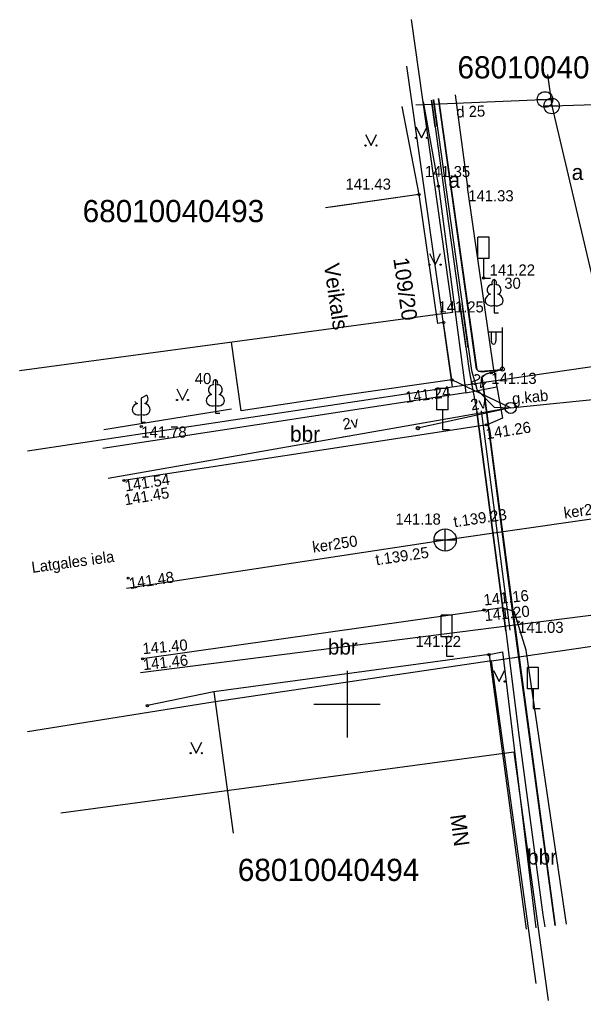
# Model space of a CAD drawing. Extents: x 728785 to 728985, y 273137 to 273208.
# Drawn here: x 728785.24 to 728810.66, y 273136.65 to 273180.84 of the extents above; entities that cross this region are included whole.
import ezdxf

# ---------------------------------------------------------------- set-up
doc = ezdxf.new("R2010")
doc.units = 0
for name, color, linetype in [('APGR_SARK_####_####_#', 7, 'Continuous'), ('APGS_ACRL_####_####_#', 7, 'Continuous'), ('APGS_ELEM_####_####_#', 7, 'Continuous'), ('APGS_VADP_ZSPR_####_I', 7, 'Continuous'), ('BUVE_BDET_####_####_#', 7, 'Continuous'), ('BUVE_EKAS_####_####_#', 7, 'Continuous'), ('BUVE_EKAS_ADRS_TKST_#', 7, 'Continuous'), ('BUVE_EKAS_RAKS_TKST_#', 7, 'Continuous'), ('CELI_CAPM_####_####_#', 7, 'Continuous'), ('CELI_CMAL_####_####_#', 7, 'Continuous'), ('CELI_CSEG_####_TKST_#', 7, 'Continuous'), ('CELI_ELEM_####_####_#', 7, 'Continuous'), ('CELI_IELA_####_TKST_#', 7, 'Continuous'), ('ELEK_ACRL_####_####_#', 7, 'Continuous'), ('ELEK_ELEM_####_####_#', 7, 'Continuous'), ('ELEK_SAIT_####_####_#', 7, 'Continuous'), ('ELEK_SAVL_####_####_#', 7, 'Continuous'), ('ELEK_VADP_ZSPR_####_I', 7, 'Continuous'), ('ELEK_VADV_ZSPR_####_#', 7, 'Continuous'), ('ELEK_VADV_ZSPR_TKST_#', 7, 'Continuous'), ('GEOD_ELEM_####_####_#', 7, 'Continuous'), ('NORB_ZOGS_ZSTP_####_#', 7, 'Continuous'), ('RELJ_AATZ_####_TKST_#', 7, 'Continuous'), ('RELJ_ELEM_####_####_#', 7, 'Continuous'), ('ROBZ_KADS_####_TKST_#', 7, 'Continuous'), ('ROBZ_UZMR_####_####_#', 7, 'Continuous'), ('SAKK_KKAN_####_####_#', 7, 'Continuous'), ('SKAN_ELEM_####_####_#', 7, 'Continuous'), ('SKAN_ELEM_PAST_TKST_#', 7, 'Continuous'), ('SKAN_VADP_PAST_####_#', 7, 'Continuous'), ('SKAN_VADP_PAST_TKST_#', 7, 'Continuous'), ('TERT_DIAM_####_TKST_#', 7, 'Continuous'), ('TERT_DZOG_####_####_#', 7, 'Continuous'), ('TERT_ELEM_####_####_#', 7, 'Continuous'), ('UDTK_ELEM_####_####_#', 7, 'Continuous'), ('UDTK_VADP_UDEN_####_#', 7, 'Continuous'), ('UDTK_VADP_UDEN_TKST_#', 7, 'Continuous')]:
    doc.layers.add(name, color=color, linetype=linetype)

msp = doc.modelspace()

# ---------------------------------------------------------------- linework, layer by layer
at = {"layer": 'APGR_SARK_####_####_#'}
for points in [[(728802.885, 273180.839), (728804.76, 273167.644)], [(728804.76, 273167.644), (728785.239, 273165.014)], [(728807.526, 273147.836), (728787.092, 273145.083)], [(728807.526, 273147.836), (728809.06, 273136.65)]]:
    msp.add_lwpolyline(points, dxfattribs=at)
at = {"layer": 'APGS_ACRL_####_####_#'}
for points in [[(728806.989, 273165.064), (728806.014, 273164.984), (728805.919, 273164.996), (728805.829, 273165.094), (728804.12, 273177.286)], [(728809.378, 273140.021), (728807.481, 273154.061), (728806.142, 273164.357), (728806.065, 273164.722), (728806.247, 273164.866), (728807.003, 273165.091)]]:
    msp.add_lwpolyline(points, dxfattribs=at)
at = {"layer": 'APGS_ELEM_####_####_#'}
for p, q in [((728807.003, 273165.091), (728807.003, 273166.974)), ((728807.003, 273166.758), (728806.368, 273166.753)), ((728806.503, 273166.754), (728806.503, 273166.362)), ((728806.713, 273166.756), (728806.713, 273166.362))]:
    msp.add_line(p, q, dxfattribs=at)
msp.add_circle((728807.003, 273165.091), 0.09, dxfattribs=at)
msp.add_ellipse((728806.608, 273166.362), major_axis=(0, 0.151), ratio=0.695971, start_param=1.570796, end_param=4.712389, dxfattribs=at)
at = {"layer": 'APGS_VADP_ZSPR_####_I'}
for points in [[(728804.129, 273177.288), (728805.803, 273165.389), (728805.847, 273165.074), (728805.919, 273164.996), (728806.11, 273164.973), (728807.003, 273165.091)], [(728807.003, 273165.091), (728806.309, 273164.885), (728806.073, 273164.759), (728806.082, 273164.765), (728806.142, 273164.357), (728807.497, 273153.999), (728809.379, 273140.022)]]:
    msp.add_lwpolyline(points, dxfattribs=at)
at = {"layer": 'BUVE_BDET_####_####_#'}
msp.add_line((728803.244, 273172.958), (728799.264, 273172.386), dxfattribs=at)
at = {"layer": 'BUVE_EKAS_####_####_#'}
for p, q in [((728803.244, 273172.958), (728799.024, 273172.352)), ((728803.244, 273172.958), (728804.078, 273167.154)), ((728804.355, 273167.194), (728804.078, 273167.154)), ((728804.727, 273164.605), (728804.355, 273167.194)), ((728795.228, 273163.212), (728794.784, 273166.3)), ((728804.727, 273164.605), (728799.907, 273163.912)), ((728799.907, 273163.912), (728795.228, 273163.212)), ((728806.402, 273152.228), (728801.322, 273151.539)), ((728806.402, 273152.228), (728808.079, 273139.861)), ((728801.322, 273151.539), (728793.998, 273150.545)), ((728793.998, 273150.545), (728794.861, 273144.179))]:
    msp.add_line(p, q, dxfattribs=at)
at = {"layer": 'CELI_CAPM_####_####_#'}
for p, q in [((728806.316, 273162.585), (728789.945, 273160.073)), ((728806.989, 273154.338), (728790.784, 273152.04))]:
    msp.add_line(p, q, dxfattribs=at)
at = {"layer": 'CELI_CMAL_####_####_#'}
for p, q in [((728804.872, 273177.45), (728805.437, 273173.285)), ((728803.431, 273177.135), (728804.116, 273173.327)), ((728804.118, 273173.334), (728805.357, 273164.023)), ((728806.63, 273164.961), (728805.437, 273173.285)), ((728805.357, 273164.023), (728788.998, 273161.513)), ((728806.402, 273152.228), (728807.002, 273152.348)), ((728807.002, 273152.348), (728808.509, 273139.914)), ((728793.998, 273150.545), (728790.999, 273149.932))]:
    msp.add_line(p, q, dxfattribs=at)
for points in [[(728806.63, 273164.961), (728807.009, 273162.88), (728806.316, 273162.585)], [(728805.357, 273164.023), (728806.752, 273164.291)], [(728809.889, 273140.085), (728808.082, 273152.433), (728807.534, 273154.175), (728806.989, 273154.338)]]:
    msp.add_lwpolyline(points, dxfattribs=at)
at = {"layer": 'CELI_ELEM_####_####_#'}
for p, q in [((728806.401, 273171.042), (728805.901, 273171.042)), ((728805.901, 273170.073), (728805.901, 273171.042)), ((728806.401, 273170.073), (728806.401, 273171.042)), ((728806.401, 273170.073), (728805.901, 273170.073)), ((728806.155, 273170.073), (728806.155, 273169.195)), ((728806.155, 273169.195), (728806.47, 273169.195)), ((728804.554, 273164.226), (728804.054, 273164.226)), ((728804.054, 273163.257), (728804.054, 273164.226)), ((728804.554, 273163.257), (728804.554, 273164.226)), ((728804.554, 273163.257), (728804.054, 273163.257)), ((728804.308, 273163.257), (728804.308, 273162.379)), ((728804.308, 273162.379), (728804.623, 273162.379)), ((728804.737, 273154.004), (728804.237, 273154.004)), ((728804.237, 273153.035), (728804.237, 273154.004)), ((728804.737, 273153.035), (728804.737, 273154.004)), ((728804.737, 273153.035), (728804.237, 273153.035)), ((728804.491, 273153.035), (728804.491, 273152.157)), ((728804.491, 273152.157), (728804.806, 273152.157)), ((728808.631, 273151.655), (728808.131, 273151.655)), ((728808.131, 273150.686), (728808.131, 273151.655)), ((728808.631, 273150.686), (728808.631, 273151.655)), ((728808.631, 273150.686), (728808.131, 273150.686)), ((728808.385, 273150.686), (728808.385, 273149.808)), ((728808.385, 273149.808), (728808.7, 273149.808))]:
    msp.add_line(p, q, dxfattribs=at)
at = {"layer": 'ELEK_ACRL_####_####_#'}
for p, q in [((728804.068, 273176.029), (728803.899, 273177.238)), ((728805.466, 273166.055), (728805.187, 273168.035)), ((728807.355, 273153.329), (728806.056, 273163.207))]:
    msp.add_line(p, q, dxfattribs=at)
for points in [[(728803.969, 273176.015), (728803.801, 273177.216)], [(728805.367, 273166.041), (728805.088, 273168.021)], [(728807.157, 273153.303), (728805.858, 273163.181)]]:
    msp.add_lwpolyline(points, dxfattribs=at)
at = {"layer": 'ELEK_ELEM_####_####_#'}
for centre, radius in [((728807.374, 273163.344), 0.25), ((728803.198, 273162.433), 0.075)]:
    msp.add_circle(centre, radius, dxfattribs=at)
at = {"layer": 'ELEK_SAIT_####_####_#'}
msp.add_line((728807.375, 273163.351), (728803.198, 273162.433), dxfattribs=at)
at = {"layer": 'ELEK_SAVL_####_####_#'}
msp.add_line((728800.117, 273162.074), (728799.814, 273162.021), dxfattribs=at)
at = {"layer": 'ELEK_VADP_ZSPR_####_I'}
msp.add_line((728805.612, 273165.025), (728805.832, 273164.242), dxfattribs=at)
for points in [[(728803.801, 273177.216), (728804.575, 273171.658), (728805.512, 273165.011)], [(728803.899, 273177.238), (728804.675, 273171.672), (728805.612, 273165.025)], [(728805.512, 273165.011), (728805.858, 273163.181)], [(728805.894, 273164.134), (728806.629, 273163.384), (728807.375, 273163.351)], [(728805.858, 273163.181), (728807.157, 273153.303)], [(728807.157, 273153.303), (728807.729, 273148.716), (728808.834, 273140.506), (728808.91, 273139.964)]]:
    msp.add_lwpolyline(points, dxfattribs=at)
msp.add_arc((728806.072, 273164.309), 0.25, 195.6985, 224.4183, dxfattribs=at)
at = {"layer": 'ELEK_VADV_ZSPR_####_#'}
for q in [(728825.007, 273165.16), (728804.727, 273164.605), (728789.226, 273160.157)]:
    msp.add_line((728807.375, 273163.351), q, dxfattribs=at)
at = {"layer": 'GEOD_ELEM_####_####_#'}
for p, q in [((728800, 273151.5), (728800, 273150)), ((728798.5, 273150), (728800, 273150)), ((728800, 273150), (728800, 273148.5)), ((728800, 273150), (728801.5, 273150))]:
    msp.add_line(p, q, dxfattribs=at)
at = {"layer": 'NORB_ZOGS_ZSTP_####_#'}
msp.add_lwpolyline([(728802.467, 273176.924), (728803.244, 273172.958)], dxfattribs=at)
at = {"layer": 'RELJ_ELEM_####_####_#'}
for centre in [(728803.244, 273172.958), (728804.118, 273173.334), (728805.479, 273173.334), (728806.155, 273169.195), (728804.355, 273167.194), (728804.727, 273164.605), (728806.501, 273164.926), (728790.725, 273162.507), (728806.281, 273162.581), (728789.945, 273160.073), (728790.133, 273155.674), (728806.177, 273154.237), (728807.716, 273153.708), (728806.402, 273152.228), (728790.784, 273152.04), (728790.999, 273149.932)]:
    msp.add_circle(centre, 0.05, dxfattribs=at)
at = {"layer": 'ROBZ_UZMR_####_####_#'}
for p, q in [((728802.684, 273178.747), (728804.732, 273164.296)), ((728804.732, 273164.296), (728816.724, 273166.025)), ((728785.596, 273161.404), (728804.732, 273164.296)), ((728806.506, 273151.952), (728818.395, 273153.682)), ((728806.506, 273151.952), (728794.058, 273150.104)), ((728808.527, 273137.409), (728806.506, 273151.952)), ((728794.058, 273150.104), (728785.596, 273148.748))]:
    msp.add_line(p, q, dxfattribs=at)
at = {"layer": 'SAKK_KKAN_####_####_#'}
msp.add_lwpolyline([(728790.691, 273151.419), (728817.008, 273154.772), (728819.184, 273141.235)], dxfattribs=at)
at = {"layer": 'SKAN_ELEM_####_####_#'}
for p, q in [((728804.423, 273156.897), (728804.423, 273157.897)), ((728803.923, 273157.397), (728804.923, 273157.397))]:
    msp.add_line(p, q, dxfattribs=at)
msp.add_circle((728804.423, 273157.397), 0.5, dxfattribs=at)
at = {"layer": 'SKAN_VADP_PAST_####_#'}
msp.add_lwpolyline([(728790.054, 273155.22), (728804.423, 273157.397), (728858.768, 273165.198)], dxfattribs=at)
at = {"layer": 'TERT_DZOG_####_####_#'}
msp.add_lwpolyline([(728789.033, 273162.366), (728794.798, 273163.301)], dxfattribs=at)
at = {"layer": 'TERT_ELEM_####_####_#'}
for p, q in [((728800.832, 273175.665), (728801.082, 273175.165)), ((728801.082, 273175.165), (728801.332, 273175.665)), ((728803.108, 273176.012), (728803.358, 273175.512)), ((728803.358, 273175.512), (728803.608, 273176.012)), ((728803.72, 273170.297), (728803.97, 273169.797)), ((728803.97, 273169.797), (728804.22, 273170.297)), ((728806.629, 273167.97), (728806.629, 273167.623)), ((728806.629, 273167.623), (728806.829, 273167.623)), ((728792.333, 273164.199), (728792.583, 273163.699)), ((728792.583, 273163.699), (728792.833, 273164.199)), ((728790.968, 273163.917), (728790.718, 273163.785)), ((728790.718, 273163.785), (728790.718, 273163.053)), ((728794.063, 273163.459), (728794.063, 273163.112)), ((728790.718, 273163.053), (728790.718, 273162.706)), ((728794.063, 273163.112), (728794.263, 273163.112)), ((728790.718, 273162.706), (728790.918, 273162.706)), ((728806.605, 273151.515), (728806.855, 273151.015)), ((728806.855, 273151.015), (728807.105, 273151.515)), ((728792.955, 273148.287), (728793.205, 273147.787)), ((728793.205, 273147.787), (728793.455, 273148.287))]:
    msp.add_line(p, q, dxfattribs=at)
for points in [[(728806.629, 273169.123), (728806.629, 273167.97)], [(728806.719, 273168.891), (728806.718, 273168.891)], [(728794.063, 273164.612), (728794.063, 273163.459)], [(728794.152, 273164.38), (728794.151, 273164.381)]]:
    msp.add_lwpolyline(points, dxfattribs=at)
for centre, radius in [((728803.108, 273175.512), 0.028), ((728803.608, 273175.512), 0.0263), ((728800.831, 273175.164), 0.028), ((728801.331, 273175.164), 0.0263), ((728803.72, 273169.797), 0.028), ((728804.22, 273169.797), 0.0263), ((728792.333, 273163.699), 0.028), ((728792.833, 273163.699), 0.0263), ((728806.605, 273151.015), 0.028), ((728807.105, 273151.015), 0.0263), ((728792.955, 273147.787), 0.028), ((728793.455, 273147.787), 0.0263)]:
    msp.add_circle(centre, radius, dxfattribs=at)
for centre, major_axis, ratio, start_param, end_param in [((728806.629, 273168.973), (0, -0.15), 0.707107, 3.14537, 5.287485), ((728806.629, 273168.973), (0, -0.15), 0.707107, 0.995701, 3.137816), ((728806.501, 273168.678), (-0.039, -0.212), 0.861323, 3.141593, 6.283185), ((728806.757, 273168.678), (0.039, -0.212), 0.861323, 0, 3.141593), ((728806.539, 273168.216), (0.307, 0.095), 0.814445, 1.570796, 4.752015), ((728806.719, 273168.216), (-0.307, 0.095), 0.814445, 1.531171, 4.712389), ((728794.063, 273164.462), (0, -0.15), 0.707107, 3.14537, 5.287485), ((728794.062, 273164.462), (0, -0.15), 0.707107, 0.995701, 3.137816), ((728793.934, 273164.167), (-0.039, -0.212), 0.861323, 3.141593, 6.283185), ((728794.191, 273164.167), (0.039, -0.212), 0.861323, 0, 3.141593), ((728790.846, 273163.761), (0.039, -0.212), 0.861323, 0, 2.225725), ((728793.973, 273163.705), (0.307, 0.095), 0.814445, 1.570796, 4.752015), ((728794.152, 273163.705), (-0.307, 0.095), 0.814445, 1.531171, 4.712389), ((728790.628, 273163.299), (0.307, 0.095), 0.814445, 1.570796, 4.752015), ((728790.59, 273163.761), (-0.039, -0.212), 0.861323, 5.499333, 6.283185), ((728790.808, 273163.299), (-0.307, 0.095), 0.814445, 1.531171, 4.712389)]:
    msp.add_ellipse(centre, major_axis=major_axis, ratio=ratio, start_param=start_param, end_param=end_param, dxfattribs=at)
at = {"layer": 'UDTK_ELEM_####_####_#'}
for p, q in [((728808.573, 273177.24), (728809.275, 273177.24)), ((728808.923, 273177.24), (728808.923, 273177.241)), ((728808.874, 273176.951), (728809.576, 273176.951)), ((728809.224, 273176.951), (728809.224, 273176.952))]:
    msp.add_line(p, q, dxfattribs=at)
for centre in [(728808.924, 273177.24), (728809.225, 273176.951)]:
    msp.add_circle(centre, 0.351, dxfattribs=at)
at = {"layer": 'UDTK_VADP_UDEN_####_#'}
for p, q in [((728803.094, 273177.001), (728809.185, 273177.251)), ((728809.225, 273176.951), (728813.21, 273177.07))]:
    msp.add_line(p, q, dxfattribs=at)
for points in [[(728809.039, 273178.363), (728809.225, 273176.951)], [(728809.225, 273176.951), (728812.761, 273161.966)]]:
    msp.add_lwpolyline(points, dxfattribs=at)

# ---------------------------------------------------------------- texts
at = {"layer": 'BUVE_EKAS_ADRS_TKST_#'}
msp.add_text('109/20', height=0.7, rotation=278.177, dxfattribs=at).set_placement((728802.082, 273170.074))
at = {"layer": 'BUVE_EKAS_RAKS_TKST_#'}
for s, rotation, p in [('Veikals ', 278.177, (728798.953, 273169.807)), ('MN', 277.723, (728804.642, 273144.992))]:
    msp.add_text(s, height=0.7, rotation=rotation, dxfattribs=at).set_placement(p)
at = {"layer": 'CELI_CSEG_####_TKST_#'}
for s, p in [('a', (728810.127, 273173.615)), ('a', (728804.574, 273173.262)), ('bbr', (728797.433, 273161.817)), ('bbr', (728799.133, 273152.231)), ('bbr', (728808.117, 273142.767))]:
    msp.add_text(s, height=0.7, dxfattribs=at).set_placement(p)
at = {"layer": 'CELI_IELA_####_TKST_#'}
msp.add_text('Latgales iela', height=0.5, rotation=7.723, dxfattribs=at).set_placement((728785.812, 273155.909))
at = {"layer": 'ELEK_VADV_ZSPR_TKST_#'}
for s, rotation, p in [('2v', 334.659, (728805.532, 273164.478)), ('g.kab', 5.5239, (728807.464, 273163.51)), ('2v', 9.978, (728805.615, 273163.226)), ('2v', 9.978, (728799.852, 273162.357))]:
    msp.add_text(s, height=0.5, rotation=rotation, dxfattribs=at).set_placement(p)
at = {"layer": 'RELJ_AATZ_####_TKST_#'}
for s, p in [(' 141.35', (728803.32, 273173.742)), (' 141.43', (728799.747, 273173.177)), (' 141.33', (728805.279, 273172.652)), (' 141.22', (728806.243, 273169.308)), (' 141.25', (728803.934, 273167.648)), ('141.13', (728806.501, 273164.426)), ('141.78', (728790.725, 273162.007)), ('141.03', (728807.716, 273153.208)), (' 141.22', (728802.903, 273152.572))]:
    msp.add_text(s, height=0.5, dxfattribs=at).set_placement(p)
for s, rotation, p in [(' 141.24', 7.4925, (728802.469, 273163.546)), ('141.26', 8.9713, (728806.3, 273161.925)), ('141.54', 8.8664, (728790.022, 273159.579)), ('141.45', 9.4698, (728789.998, 273158.953)), ('141.48', 8.6116, (728790.208, 273155.18)), ('141.16', 6.1077, (728806.182, 273154.438)), ('141.20', 5.8857, (728806.222, 273153.736)), ('141.40', 5.0837, (728790.799, 273152.247)), ('141.46', 6.1624, (728790.823, 273151.525))]:
    msp.add_text(s, height=0.5, rotation=rotation, dxfattribs=at).set_placement(p)
at = {"layer": 'ROBZ_KADS_####_TKST_#'}
for s, p in [('68010040724', (728804.981, 273178.19)), ('68010040493', (728788.083, 273171.713)), ('68010040494', (728795.078, 273142.03))]:
    msp.add_text(s, height=1, dxfattribs=at).set_placement(p)
at = {"layer": 'SKAN_ELEM_PAST_TKST_#'}
msp.add_text(' 141.18', height=0.5, dxfattribs=at).set_placement((728801.997, 273158.086))
at = {"layer": 'SKAN_VADP_PAST_TKST_#'}
for s, p in [('ker250', (728809.808, 273158.357)), ('t.139.23', (728804.84, 273157.963)), ('ker250', (728798.476, 273156.82)), ('t.139.25', (728801.322, 273156.252))]:
    msp.add_text(s, height=0.5, rotation=8.258, dxfattribs=at).set_placement(p)
at = {"layer": 'TERT_DIAM_####_TKST_#'}
for s, p in [('30', (728807.089, 273168.713)), ('40', (728793.136, 273164.419))]:
    msp.add_text(s, height=0.5, dxfattribs=at).set_placement(p)
at = {"layer": 'UDTK_VADP_UDEN_TKST_#'}
msp.add_text('d 25', height=0.5, rotation=2.3475, dxfattribs=at).set_placement((728804.936, 273176.424))

doc.saveas('drawing.dxf')
